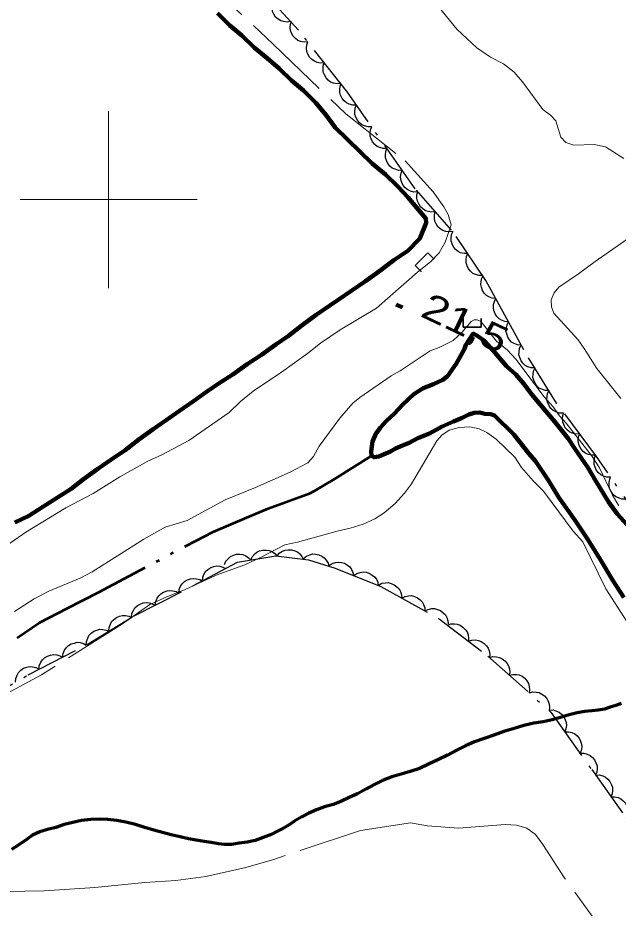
# Model space of a CAD drawing. Extents: x 356765 to 358572, y 5103174 to 5104650.
# Drawn here: x 357194.9 to 357228.8, y 5104260 to 5104310.3 of the extents above; entities that cross this region are included whole.
import ezdxf

# ---------------------------------------------------------------- set-up
doc = ezdxf.new("R2010")
doc.units = 0
doc.header["$LTSCALE"] = 0.6
for name, pattern in [('DASH_DOUBLE_DOT', [9.2, 5, -1.2, 0.3, -1.2, 0.3, -1.2]), ('DOT_DASHED', [7.7, 5, -1.2, 0.3, -1.2]), ('LONG_DASHED', [7.5, 6, -1.5])]:
    doc.linetypes.add(name, pattern=pattern)
for name, color, linetype, lineweight in [('2', 7, 'Continuous', 13), ('22', 7, 'Continuous', 35), ('26', 7, 'Continuous', 35), ('3', 7, 'Continuous', 140), ('4', 7, 'Continuous', 90), ('44', 7, 'Continuous', 25), ('61', 7, 'Continuous', 13)]:
    doc.layers.add(name, color=color, linetype=linetype, lineweight=lineweight)

msp = doc.modelspace()

# ---------------------------------------------------------------- linework, layer by layer
at = {"layer": '2', "linetype": 'LONG_DASHED'}
for points in [[(357204.9, 5104312.9), (357209.3, 5104308.78), (357213.39, 5104304.84), (357216.74, 5104302.19), (357218.32, 5104300.43), (357218.93, 5104299.6), (357219.18, 5104299.16)], [(357229.1, 5104302.32), (357228.05, 5104302.98), (357227.42, 5104303.12), (357226.27, 5104303.07), (357225.81, 5104303.22), (357225.54, 5104303.53), (357225.26, 5104304.45), (357224.95, 5104304.76), (357224.52, 5104305.09), (357223.37, 5104306.65), (357222.9, 5104307.2), (357222.29, 5104307.67), (357221.56, 5104308.05), (357220.79, 5104308.57), (357219.66, 5104309.62), (357218.42, 5104311.14)], [(357219.18, 5104299.16), (357219.35, 5104298.58), (357219, 5104297.6), (357218.66, 5104297), (357218.17, 5104296.48), (357217.45, 5104295.9), (357215.13, 5104293.86), (357213.07, 5104292.65)], [(357228.92, 5104288.76), (357227.56, 5104290.46), (357226.86, 5104291.59), (357226.49, 5104292.09), (357225.15, 5104293.59), (357225.01, 5104293.94), (357224.99, 5104294.34), (357225.16, 5104294.73), (357225.42, 5104295.05), (357226.54, 5104295.8), (357227.47, 5104296.51), (357230.04, 5104298.3)], [(357211.89, 5104286.07), (357213.05, 5104287.66), (357213.79, 5104288.51), (357214.18, 5104288.83), (357215.96, 5104290.05), (357216.47, 5104290.33), (357218.15, 5104291.46), (357218.66, 5104291.65), (357219.46, 5104292.05), (357219.94, 5104292.5), (357220.48, 5104293.11), (357220.64, 5104293.21), (357220.82, 5104293.21), (357221.02, 5104293.11), (357221.91, 5104292.01), (357222.52, 5104291.49), (357223, 5104290.99), (357224.6, 5104288.87), (357225.11, 5104288.3), (357225.46, 5104287.79), (357225.83, 5104287.38), (357227.27, 5104285.55), (357227.72, 5104284.86), (357228.45, 5104283.3), (357228.81, 5104282.71)], [(357229.26, 5104276.18), (357228.08, 5104278.01), (357226.78, 5104280.67), (357226.24, 5104281.28), (357224.56, 5104283.54), (357223.97, 5104284.11), (357223.32, 5104284.88), (357222.94, 5104285.45), (357221.88, 5104286.47), (357221.36, 5104286.84), (357220.93, 5104287.05), (357220.4, 5104287.16), (357219.79, 5104287.13), (357219.24, 5104286.97), (357218.82, 5104286.7), (357218.53, 5104286.38), (357217.11, 5104283.94), (357216.71, 5104283.42), (357216.19, 5104282.84), (357215.57, 5104282.32), (357215.04, 5104281.97), (357214.37, 5104281.67), (357213.65, 5104281.45), (357212.9, 5104281.28), (357210.67, 5104280.65), (357209.96, 5104280.51), (357208.62, 5104279.8), (357207.7, 5104279.37), (357206.07, 5104278.79), (357204.29, 5104277.96), (357203.33, 5104277.59), (357202.33, 5104277.13), (357200.79, 5104276.05), (357196.21, 5104273.16), (357193.08, 5104271.49)], [(357190.89, 5104274.32), (357195.8, 5104277.46), (357196.62, 5104277.88), (357198.4, 5104278.63), (357199.08, 5104278.97), (357202, 5104280.82), (357203.19, 5104281.5), (357204.43, 5104281.87), (357206.59, 5104283.05), (357208.3, 5104283.74), (357210.25, 5104284.61), (357211.25, 5104285.13), (357211.57, 5104285.49), (357211.89, 5104286.07)], [(357228.44, 5104257.98), (357225.72, 5104261.72), (357224.52, 5104263.59), (357224.11, 5104264.15), (357223.61, 5104264.5), (357223.04, 5104264.68), (357222.4, 5104264.71), (357219.75, 5104264.51), (357218, 5104264.63), (357217.05, 5104264.8), (357214.23, 5104264.38), (357209.38, 5104262.76), (357207.75, 5104262.29), (357205.49, 5104261.78), (357203.79, 5104261.55), (357202.05, 5104261.44), (357199.23, 5104261.15), (357196.37, 5104260.97), (357194.18, 5104260.92)]]:
    msp.add_lwpolyline(points, dxfattribs=at)
at = {"layer": '2'}
msp.add_lwpolyline([(357192.95, 5104279.59), (357195.33, 5104281.21), (357197.59, 5104282.6), (357199.13, 5104283.41), (357200.64, 5104284.34), (357202.22, 5104285.23), (357203, 5104285.58), (357204.54, 5104286.39), (357206.81, 5104287.98), (357207.45, 5104288.6), (357208.17, 5104289.18), (357209.76, 5104290.26), (357211.24, 5104291.31), (357211.96, 5104291.89), (357213.07, 5104292.65)], dxfattribs=at)
at = {"layer": '22', "linetype": 'LONG_DASHED', "lineweight": 70}
for points in [[(357228.94, 5104271.54), (357228.65, 5104271.43), (357228.33, 5104271.33), (357228.01, 5104271.23), (357227.65, 5104271.17), (357227.29, 5104271.13), (357226.89, 5104271.09), (357226.46, 5104271.01), (357226, 5104270.9), (357225.52, 5104270.76), (357225.05, 5104270.62), (357224.53, 5104270.51), (357224.02, 5104270.43), (357223.44, 5104270.3), (357222.9, 5104270.13), (357222.32, 5104269.97), (357221.75, 5104269.76), (357221.2, 5104269.57), (357220.67, 5104269.37), (357220.16, 5104269.15)], [(357220.16, 5104269.15), (357219.66, 5104268.9), (357219.13, 5104268.63), (357218.6, 5104268.37), (357218.06, 5104268.12), (357217.56, 5104267.88), (357217.03, 5104267.7), (357216.52, 5104267.55), (357215.99, 5104267.4), (357215.51, 5104267.21), (357215.01, 5104266.97), (357214.53, 5104266.71), (357214.05, 5104266.44), (357213.58, 5104266.23), (357213.11, 5104266.01), (357212.68, 5104265.84), (357212.2, 5104265.7), (357211.74, 5104265.53), (357211.31, 5104265.36), (357210.91, 5104265.15), (357210.52, 5104264.92), (357210.19, 5104264.7), (357209.87, 5104264.5), (357209.54, 5104264.33), (357209.18, 5104264.15), (357208.73, 5104263.97), (357208.28, 5104263.8), (357207.82, 5104263.72), (357207.37, 5104263.65), (357206.95, 5104263.59), (357206.56, 5104263.58), (357206.21, 5104263.62), (357205.8, 5104263.7), (357205.4, 5104263.76), (357204.95, 5104263.82), (357204.52, 5104263.91), (357204.05, 5104264.01), (357203.54, 5104264.13), (357203.04, 5104264.26), (357202.55, 5104264.4), (357202.04, 5104264.55), (357201.52, 5104264.72), (357200.98, 5104264.84), (357200.47, 5104264.94), (357199.96, 5104265), (357199.48, 5104265.01), (357198.98, 5104265), (357198.48, 5104264.94), (357197.99, 5104264.82), (357197.5, 5104264.71), (357197.03, 5104264.55), (357196.56, 5104264.43), (357196.11, 5104264.29), (357195.71, 5104264.11), (357195.34, 5104263.84), (357194.94, 5104263.57), (357194.52, 5104263.29)]]:
    msp.add_lwpolyline(points, dxfattribs=at)
at = {"layer": '26'}
for p, q in [((357217.32, 5104296.28), (357218.03, 5104296.99)), ((357218.03, 5104296.99), (357218.38, 5104296.64)), ((357217.32, 5104296.28), (357217.67, 5104295.92)), ((357220.03, 5104292.79), (357220.03, 5104293.29)), ((357221.04, 5104292.79), (357221.04, 5104293.29)), ((357221.04, 5104292.79), (357220.03, 5104292.79))]:
    msp.add_line(p, q, dxfattribs=at)
at = {"layer": '3'}
msp.add_line((357216.23, 5104294.07), (357216.59, 5104293.9), dxfattribs=at)
at = {"layer": '4'}
for points in [[(357201.71, 5104286.45), (357202.52, 5104287.03), (357203.26, 5104287.55), (357204, 5104288.08), (357204.79, 5104288.62), (357205.53, 5104289.14), (357206.24, 5104289.63), (357207.02, 5104290.13), (357207.83, 5104290.71), (357208.63, 5104291.24), (357209.45, 5104291.82), (357210.16, 5104292.31), (357210.94, 5104292.91), (357211.72, 5104293.5), (357212.49, 5104294.01), (357212.97, 5104294.33), (357214.5, 5104295.39), (357215.32, 5104295.97), (357216.1, 5104296.57), (357216.89, 5104297.11), (357217.58, 5104297.81), (357217.93, 5104298.69), (357217.92, 5104298.94), (357216.89, 5104300.13), (357216.34, 5104300.73), (357215.63, 5104301.42), (357214.89, 5104302.03), (357214.19, 5104302.71), (357213.49, 5104303.4), (357212.79, 5104304.08), (357212.28, 5104304.76), (357211.7, 5104305.47), (357211, 5104306.16), (357210.33, 5104306.73), (357209.63, 5104307.41), (357208.96, 5104307.98), (357208.22, 5104308.59), (357207.52, 5104309.27), (357206.85, 5104309.84), (357206.15, 5104310.52)], [(357229.29, 5104281.64), (357228.72, 5104282.26), (357228.23, 5104282.94), (357227.5, 5104284.13), (357227.07, 5104284.87), (357226.34, 5104285.91), (357225.95, 5104286.5), (357225.2, 5104287.45), (357224.39, 5104288.41), (357223.89, 5104289), (357223.45, 5104289.6), (357222.99, 5104290.12), (357222.47, 5104290.6), (357221.58, 5104291.63), (357221.23, 5104292.03), (357220.8, 5104292.33), (357220.59, 5104292.43), (357220.18, 5104291.79), (357220.1, 5104291.57), (357219.98, 5104291.37), (357219.79, 5104291.03), (357219.63, 5104290.73), (357219.13, 5104290.02), (357218.87, 5104289.82), (357218.34, 5104289.58), (357217.77, 5104289.35), (357217.24, 5104289.01), (357216.61, 5104288.43), (357216.13, 5104287.91), (357215.7, 5104287.51), (357215.34, 5104287.12), (357215.09, 5104286.77), (357214.9, 5104286.34), (357214.83, 5104285.78), (357214.84, 5104285.53), (357214.99, 5104285.45), (357215.26, 5104285.49), (357215.52, 5104285.6), (357215.91, 5104285.77), (357216.21, 5104285.95), (357216.6, 5104286.12), (357216.98, 5104286.26), (357217.47, 5104286.53), (357218.12, 5104286.8), (357218.83, 5104287.19), (357219.48, 5104287.47), (357219.93, 5104287.66), (357220.34, 5104287.87), (357220.64, 5104287.96), (357220.95, 5104287.98), (357221.25, 5104287.91), (357221.58, 5104287.88), (357221.79, 5104287.81), (357222.88, 5104286.74), (357223.73, 5104285.67), (357224.11, 5104285.23), (357224.84, 5104284.13), (357225.43, 5104283.18), (357226.34, 5104281.87), (357227.07, 5104280.8), (357227.78, 5104279.66), (357228.48, 5104278.49), (357229.1, 5104277.53)], [(357194.7, 5104281.76), (357195.5, 5104282.15), (357196.28, 5104282.65), (357197.11, 5104283.17), (357197.88, 5104283.67), (357198.58, 5104284.21), (357199.4, 5104284.79), (357200.13, 5104285.31), (357200.93, 5104285.85), (357201.71, 5104286.45)]]:
    msp.add_lwpolyline(points, dxfattribs=at)
at = {"layer": '4', "linetype": 'DASH_DOUBLE_DOT', "lineweight": 53}
msp.add_lwpolyline([(357194.84, 5104275.26), (357196.09, 5104276.09), (357197.69, 5104276.92), (357199.42, 5104277.82), (357204.39, 5104280.45), (357205.91, 5104281.23), (357207.8, 5104282.04), (357209.02, 5104282.55), (357211.39, 5104283.43), (357211.8, 5104283.64), (357212.18, 5104283.88), (357212.77, 5104284.23), (357214.84, 5104285.53)], dxfattribs=at)
at = {"layer": '44', "linetype": 'DOT_DASHED'}
for points in [[(357253.82, 5104257.56), (357250.95, 5104260.53), (357248.13, 5104262.88), (357245.1, 5104265.55), (357239.57, 5104270.78), (357234.96, 5104275.89), (357230.8, 5104280.75), (357227.55, 5104285.5), (357225.3, 5104288.51), (357223.44, 5104291.51), (357222.38, 5104293.47), (357221.31, 5104295.44), (357219.37, 5104298.28), (357217.32, 5104300.6), (357213.49, 5104306.06), (357210.73, 5104309.56), (357208.16, 5104312.36)], [(357191.98, 5104271.17), (357195.46, 5104273.16), (357198.76, 5104274.85), (357201.45, 5104276.49), (357204.76, 5104278.18), (357207.28, 5104279.52), (357209.45, 5104279.88), (357211.29, 5104279.65), (357212.8, 5104279.19), (357215.37, 5104278.16), (357218.67, 5104276.32), (357221.42, 5104274.21), (357224.97, 5104271.06), (357227.28, 5104267.81), (357230.03, 5104263.93), (357232.39, 5104260.07), (357235.22, 5104254.58), (357236.78, 5104251.75), (357238.04, 5104249.08), (357238.95, 5104245.44), (357239.46, 5104241.43), (357239.4, 5104236.76), (357239.19, 5104232.18), (357239.27, 5104228.8)]]:
    msp.add_lwpolyline(points, dxfattribs=at)
at = {"layer": '44'}
for points in [[(357210.28, 5104310.05), (357210.08, 5104310.02), (357209.87, 5104310.05), (357209.72, 5104310.09), (357209.57, 5104310.19), (357209.43, 5104310.31), (357209.33, 5104310.47), (357209.25, 5104310.62), (357209.23, 5104310.79), (357209.23, 5104310.98), (357209.27, 5104311.15)], [(357211.25, 5104308.9), (357211.04, 5104308.89), (357210.84, 5104308.93), (357210.69, 5104308.99), (357210.55, 5104309.09), (357210.42, 5104309.23), (357210.33, 5104309.4), (357210.27, 5104309.55), (357210.25, 5104309.72), (357210.27, 5104309.91), (357210.32, 5104310.08)], [(357212.18, 5104307.72), (357211.97, 5104307.71), (357211.77, 5104307.75), (357211.62, 5104307.81), (357211.48, 5104307.92), (357211.35, 5104308.05), (357211.26, 5104308.22), (357211.19, 5104308.37), (357211.18, 5104308.55), (357211.19, 5104308.73), (357211.25, 5104308.9)], [(357213.11, 5104306.55), (357212.9, 5104306.53), (357212.7, 5104306.58), (357212.54, 5104306.63), (357212.4, 5104306.74), (357212.28, 5104306.87), (357212.19, 5104307.04), (357212.12, 5104307.19), (357212.11, 5104307.37), (357212.12, 5104307.55), (357212.18, 5104307.72)], [(357214, 5104305.34), (357213.79, 5104305.34), (357213.59, 5104305.39), (357213.44, 5104305.46), (357213.31, 5104305.57), (357213.19, 5104305.71), (357213.1, 5104305.89), (357213.05, 5104306.04), (357213.05, 5104306.22), (357213.07, 5104306.4), (357213.13, 5104306.57)], [(357214.86, 5104304.11), (357214.65, 5104304.11), (357214.45, 5104304.16), (357214.3, 5104304.23), (357214.17, 5104304.34), (357214.05, 5104304.48), (357213.97, 5104304.66), (357213.91, 5104304.81), (357213.91, 5104304.99), (357213.93, 5104305.17), (357214, 5104305.34)], [(357215.72, 5104302.88), (357215.51, 5104302.88), (357215.31, 5104302.94), (357215.16, 5104303), (357215.03, 5104303.11), (357214.91, 5104303.26), (357214.83, 5104303.43), (357214.77, 5104303.58), (357214.77, 5104303.76), (357214.79, 5104303.94), (357214.86, 5104304.11)], [(357216.58, 5104301.66), (357216.37, 5104301.65), (357216.18, 5104301.71), (357216.02, 5104301.77), (357215.89, 5104301.89), (357215.77, 5104302.03), (357215.69, 5104302.2), (357215.63, 5104302.36), (357215.63, 5104302.53), (357215.65, 5104302.71), (357215.72, 5104302.88)], [(357217.44, 5104300.43), (357217.23, 5104300.42), (357217.04, 5104300.48), (357216.89, 5104300.55), (357216.75, 5104300.66), (357216.63, 5104300.8), (357216.55, 5104300.97), (357216.5, 5104301.13), (357216.49, 5104301.3), (357216.52, 5104301.49), (357216.58, 5104301.66)], [(357218.45, 5104299.32), (357218.25, 5104299.29), (357218.05, 5104299.32), (357217.89, 5104299.37), (357217.74, 5104299.47), (357217.61, 5104299.6), (357217.51, 5104299.76), (357217.44, 5104299.91), (357217.41, 5104300.08), (357217.41, 5104300.27), (357217.46, 5104300.44)], [(357219.45, 5104298.19), (357219.24, 5104298.17), (357219.04, 5104298.2), (357218.88, 5104298.25), (357218.73, 5104298.35), (357218.6, 5104298.47), (357218.5, 5104298.64), (357218.43, 5104298.78), (357218.4, 5104298.96), (357218.41, 5104299.14), (357218.45, 5104299.32)], [(357220.28, 5104296.95), (357220.07, 5104296.95), (357219.88, 5104297), (357219.73, 5104297.07), (357219.59, 5104297.19), (357219.48, 5104297.33), (357219.4, 5104297.5), (357219.34, 5104297.66), (357219.34, 5104297.83), (357219.37, 5104298.02), (357219.43, 5104298.18)], [(357221.13, 5104295.71), (357220.92, 5104295.71), (357220.72, 5104295.77), (357220.57, 5104295.83), (357220.44, 5104295.95), (357220.32, 5104296.09), (357220.24, 5104296.26), (357220.19, 5104296.42), (357220.19, 5104296.6), (357220.21, 5104296.78), (357220.28, 5104296.95)], [(357221.87, 5104294.41), (357221.66, 5104294.43), (357221.48, 5104294.5), (357221.33, 5104294.59), (357221.21, 5104294.72), (357221.11, 5104294.87), (357221.05, 5104295.05), (357221.01, 5104295.21), (357221.03, 5104295.39), (357221.07, 5104295.57), (357221.16, 5104295.72)], [(357222.59, 5104293.09), (357222.38, 5104293.11), (357222.19, 5104293.19), (357222.05, 5104293.27), (357221.93, 5104293.4), (357221.83, 5104293.55), (357221.76, 5104293.73), (357221.73, 5104293.89), (357221.74, 5104294.07), (357221.79, 5104294.25), (357221.87, 5104294.41)], [(357223.3, 5104291.77), (357223.09, 5104291.79), (357222.9, 5104291.87), (357222.76, 5104291.95), (357222.64, 5104292.08), (357222.54, 5104292.23), (357222.48, 5104292.41), (357222.44, 5104292.57), (357222.46, 5104292.75), (357222.5, 5104292.93), (357222.59, 5104293.09)], [(357224.08, 5104290.49), (357223.87, 5104290.49), (357223.67, 5104290.56), (357223.53, 5104290.63), (357223.4, 5104290.76), (357223.29, 5104290.9), (357223.22, 5104291.08), (357223.17, 5104291.24), (357223.18, 5104291.41), (357223.21, 5104291.6), (357223.28, 5104291.76)], [(357224.87, 5104289.21), (357224.66, 5104289.22), (357224.47, 5104289.29), (357224.32, 5104289.36), (357224.19, 5104289.48), (357224.08, 5104289.63), (357224.01, 5104289.81), (357223.96, 5104289.96), (357223.97, 5104290.14), (357224, 5104290.32), (357224.08, 5104290.49)], [(357225.66, 5104287.94), (357225.45, 5104287.94), (357225.26, 5104288.01), (357225.11, 5104288.09), (357224.98, 5104288.21), (357224.87, 5104288.35), (357224.8, 5104288.53), (357224.75, 5104288.69), (357224.76, 5104288.86), (357224.79, 5104289.05), (357224.87, 5104289.21)], [(357226.6, 5104286.77), (357226.39, 5104286.76), (357226.2, 5104286.81), (357226.04, 5104286.87), (357225.91, 5104286.98), (357225.78, 5104287.12), (357225.7, 5104287.29), (357225.64, 5104287.44), (357225.63, 5104287.61), (357225.65, 5104287.8), (357225.7, 5104287.97)], [(357227.5, 5104285.57), (357227.29, 5104285.56), (357227.1, 5104285.61), (357226.94, 5104285.67), (357226.8, 5104285.78), (357226.68, 5104285.91), (357226.59, 5104286.08), (357226.53, 5104286.24), (357226.52, 5104286.41), (357226.54, 5104286.6), (357226.6, 5104286.77)], [(357228.35, 5104284.33), (357228.14, 5104284.33), (357227.95, 5104284.39), (357227.8, 5104284.45), (357227.66, 5104284.57), (357227.55, 5104284.71), (357227.47, 5104284.89), (357227.41, 5104285.04), (357227.41, 5104285.22), (357227.44, 5104285.4), (357227.5, 5104285.57)], [(357229.2, 5104283.09), (357228.99, 5104283.09), (357228.79, 5104283.15), (357228.64, 5104283.22), (357228.51, 5104283.33), (357228.39, 5104283.47), (357228.31, 5104283.65), (357228.26, 5104283.8), (357228.26, 5104283.98), (357228.28, 5104284.16), (357228.35, 5104284.33)], [(357206.55, 5104279.4), (357206.63, 5104279.59), (357206.77, 5104279.74), (357206.89, 5104279.85), (357207.05, 5104279.92), (357207.23, 5104279.97), (357207.42, 5104279.97), (357207.59, 5104279.95), (357207.75, 5104279.88), (357207.9, 5104279.77), (357208.03, 5104279.64)], [(357208.03, 5104279.64), (357208.11, 5104279.83), (357208.25, 5104279.99), (357208.37, 5104280.09), (357208.53, 5104280.17), (357208.71, 5104280.21), (357208.9, 5104280.21), (357209.07, 5104280.19), (357209.23, 5104280.12), (357209.38, 5104280.02), (357209.5, 5104279.89)], [(357209.51, 5104279.87), (357209.64, 5104280.03), (357209.82, 5104280.14), (357209.97, 5104280.21), (357210.14, 5104280.23), (357210.32, 5104280.22), (357210.51, 5104280.17), (357210.66, 5104280.1), (357210.79, 5104279.99), (357210.91, 5104279.85), (357210.99, 5104279.69)], [(357211, 5104279.74), (357211.17, 5104279.87), (357211.36, 5104279.94), (357211.51, 5104279.99), (357211.69, 5104279.98), (357211.87, 5104279.94), (357212.04, 5104279.86), (357212.18, 5104279.77), (357212.29, 5104279.63), (357212.39, 5104279.47), (357212.44, 5104279.3)], [(357205.3, 5104278.47), (357205.32, 5104278.67), (357205.4, 5104278.86), (357205.48, 5104279), (357205.61, 5104279.12), (357205.77, 5104279.22), (357205.95, 5104279.28), (357206.11, 5104279.32), (357206.28, 5104279.3), (357206.46, 5104279.25), (357206.62, 5104279.17)], [(357212.45, 5104279.33), (357212.62, 5104279.45), (357212.82, 5104279.51), (357212.98, 5104279.53), (357213.15, 5104279.51), (357213.33, 5104279.46), (357213.49, 5104279.36), (357213.62, 5104279.26), (357213.72, 5104279.12), (357213.8, 5104278.95), (357213.84, 5104278.77)], [(357213.84, 5104278.77), (357214.02, 5104278.89), (357214.21, 5104278.95), (357214.37, 5104278.98), (357214.55, 5104278.96), (357214.72, 5104278.9), (357214.89, 5104278.8), (357215.02, 5104278.7), (357215.12, 5104278.56), (357215.2, 5104278.39), (357215.23, 5104278.21)], [(357203.97, 5104277.78), (357203.99, 5104277.98), (357204.07, 5104278.17), (357204.16, 5104278.31), (357204.29, 5104278.43), (357204.45, 5104278.52), (357204.63, 5104278.58), (357204.79, 5104278.61), (357204.97, 5104278.59), (357205.15, 5104278.54), (357205.3, 5104278.46)], [(357215.24, 5104278.23), (357215.43, 5104278.33), (357215.63, 5104278.36), (357215.79, 5104278.37), (357215.96, 5104278.32), (357216.13, 5104278.25), (357216.28, 5104278.13), (357216.4, 5104278.01), (357216.48, 5104277.86), (357216.54, 5104277.68), (357216.55, 5104277.5)], [(357202.63, 5104277.09), (357202.66, 5104277.3), (357202.74, 5104277.49), (357202.83, 5104277.63), (357202.96, 5104277.74), (357203.11, 5104277.84), (357203.3, 5104277.9), (357203.46, 5104277.93), (357203.63, 5104277.91), (357203.81, 5104277.86), (357203.97, 5104277.78)], [(357216.55, 5104277.5), (357216.74, 5104277.59), (357216.94, 5104277.63), (357217.1, 5104277.64), (357217.27, 5104277.59), (357217.44, 5104277.52), (357217.59, 5104277.4), (357217.71, 5104277.28), (357217.79, 5104277.13), (357217.85, 5104276.95), (357217.86, 5104276.77)], [(357201.29, 5104276.41), (357201.32, 5104276.62), (357201.4, 5104276.8), (357201.49, 5104276.94), (357201.62, 5104277.06), (357201.78, 5104277.16), (357201.96, 5104277.22), (357202.12, 5104277.25), (357202.29, 5104277.23), (357202.47, 5104277.18), (357202.63, 5104277.09)], [(357217.86, 5104276.77), (357218.05, 5104276.86), (357218.25, 5104276.9), (357218.41, 5104276.91), (357218.58, 5104276.86), (357218.75, 5104276.79), (357218.9, 5104276.67), (357219.02, 5104276.55), (357219.1, 5104276.4), (357219.16, 5104276.22), (357219.17, 5104276.04)], [(357200.02, 5104275.62), (357200.03, 5104275.83), (357200.1, 5104276.02), (357200.17, 5104276.17), (357200.3, 5104276.29), (357200.44, 5104276.4), (357200.62, 5104276.47), (357200.78, 5104276.52), (357200.96, 5104276.51), (357201.14, 5104276.47), (357201.3, 5104276.4)], [(357219.13, 5104275.97), (357219.32, 5104276.04), (357219.53, 5104276.04), (357219.69, 5104276.02), (357219.85, 5104275.96), (357220.01, 5104275.86), (357220.14, 5104275.72), (357220.24, 5104275.59), (357220.3, 5104275.42), (357220.33, 5104275.24), (357220.32, 5104275.06)], [(357198.74, 5104274.84), (357198.75, 5104275.05), (357198.82, 5104275.24), (357198.89, 5104275.38), (357199.02, 5104275.51), (357199.16, 5104275.62), (357199.34, 5104275.69), (357199.5, 5104275.74), (357199.68, 5104275.73), (357199.86, 5104275.69), (357200.02, 5104275.62)], [(357197.4, 5104274.16), (357197.43, 5104274.36), (357197.51, 5104274.55), (357197.6, 5104274.69), (357197.73, 5104274.81), (357197.89, 5104274.91), (357198.07, 5104274.96), (357198.23, 5104275), (357198.4, 5104274.98), (357198.58, 5104274.93), (357198.74, 5104274.84)], [(357220.32, 5104275.06), (357220.51, 5104275.12), (357220.72, 5104275.13), (357220.88, 5104275.11), (357221.04, 5104275.04), (357221.2, 5104274.94), (357221.33, 5104274.8), (357221.43, 5104274.67), (357221.49, 5104274.51), (357221.52, 5104274.32), (357221.51, 5104274.14)], [(357196.07, 5104273.47), (357196.09, 5104273.68), (357196.18, 5104273.87), (357196.26, 5104274.01), (357196.39, 5104274.12), (357196.55, 5104274.22), (357196.73, 5104274.28), (357196.89, 5104274.31), (357197.07, 5104274.29), (357197.25, 5104274.24), (357197.4, 5104274.16)], [(357221.5, 5104274.14), (357221.7, 5104274.19), (357221.91, 5104274.18), (357222.07, 5104274.15), (357222.23, 5104274.07), (357222.38, 5104273.96), (357222.5, 5104273.81), (357222.58, 5104273.67), (357222.63, 5104273.5), (357222.65, 5104273.32), (357222.62, 5104273.14)], [(357194.75, 5104272.75), (357194.77, 5104272.96), (357194.84, 5104273.15), (357194.92, 5104273.3), (357195.05, 5104273.42), (357195.2, 5104273.53), (357195.38, 5104273.59), (357195.54, 5104273.63), (357195.71, 5104273.62), (357195.89, 5104273.58), (357196.05, 5104273.5)], [(357222.62, 5104273.14), (357222.83, 5104273.19), (357223.03, 5104273.18), (357223.19, 5104273.16), (357223.35, 5104273.08), (357223.5, 5104272.97), (357223.62, 5104272.82), (357223.71, 5104272.68), (357223.75, 5104272.51), (357223.77, 5104272.32), (357223.75, 5104272.15)], [(357223.75, 5104272.15), (357223.95, 5104272.2), (357224.15, 5104272.19), (357224.31, 5104272.16), (357224.47, 5104272.08), (357224.62, 5104271.97), (357224.74, 5104271.82), (357224.83, 5104271.68), (357224.87, 5104271.51), (357224.89, 5104271.33), (357224.87, 5104271.15)], [(357224.89, 5104271.17), (357225.1, 5104271.18), (357225.3, 5104271.12), (357225.45, 5104271.06), (357225.58, 5104270.94), (357225.7, 5104270.8), (357225.79, 5104270.63), (357225.84, 5104270.48), (357225.85, 5104270.3), (357225.82, 5104270.12), (357225.76, 5104269.95)], [(357225.76, 5104269.95), (357225.97, 5104269.95), (357226.16, 5104269.9), (357226.32, 5104269.83), (357226.45, 5104269.72), (357226.57, 5104269.58), (357226.65, 5104269.41), (357226.71, 5104269.25), (357226.72, 5104269.08), (357226.69, 5104268.89), (357226.63, 5104268.73)], [(357226.63, 5104268.73), (357226.84, 5104268.73), (357227.03, 5104268.68), (357227.19, 5104268.61), (357227.32, 5104268.5), (357227.44, 5104268.36), (357227.52, 5104268.19), (357227.58, 5104268.03), (357227.58, 5104267.86), (357227.56, 5104267.67), (357227.5, 5104267.5)], [(357227.5, 5104267.5), (357227.71, 5104267.51), (357227.9, 5104267.45), (357228.05, 5104267.39), (357228.19, 5104267.27), (357228.31, 5104267.13), (357228.39, 5104266.96), (357228.45, 5104266.81), (357228.45, 5104266.63), (357228.43, 5104266.45), (357228.36, 5104266.28)], [(357228.36, 5104266.28), (357228.57, 5104266.28), (357228.77, 5104266.23), (357228.92, 5104266.16), (357229.06, 5104266.05), (357229.18, 5104265.91), (357229.26, 5104265.74), (357229.31, 5104265.58), (357229.32, 5104265.41), (357229.3, 5104265.22), (357229.23, 5104265.06)]]:
    msp.add_lwpolyline(points, dxfattribs=at)
at = {"layer": '61'}
for p, q in [((357200, 5104295), (357200, 5104305)), ((357195, 5104300), (357205, 5104300))]:
    msp.add_line(p, q, dxfattribs=at)

# ---------------------------------------------------------------- texts
at = {"layer": '3', "width": 1.3}
msp.add_text('21,5   ', height=1.5, rotation=334.619, dxfattribs=at).set_placement((357217.53, 5104293.44))

doc.saveas('drawing.dxf')
